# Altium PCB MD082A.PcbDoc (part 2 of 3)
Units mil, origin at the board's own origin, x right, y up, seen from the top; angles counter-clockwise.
Board outline 3650 x 4750 mil, 4 copper layers (Top Layer, GND Layer, Power Layer, Bottom Layer), stack 61.2 mil thick; 201 components, 105 nets, 514 pads, 1209 vias.
Unrouted connection lines stored in the file: 46.
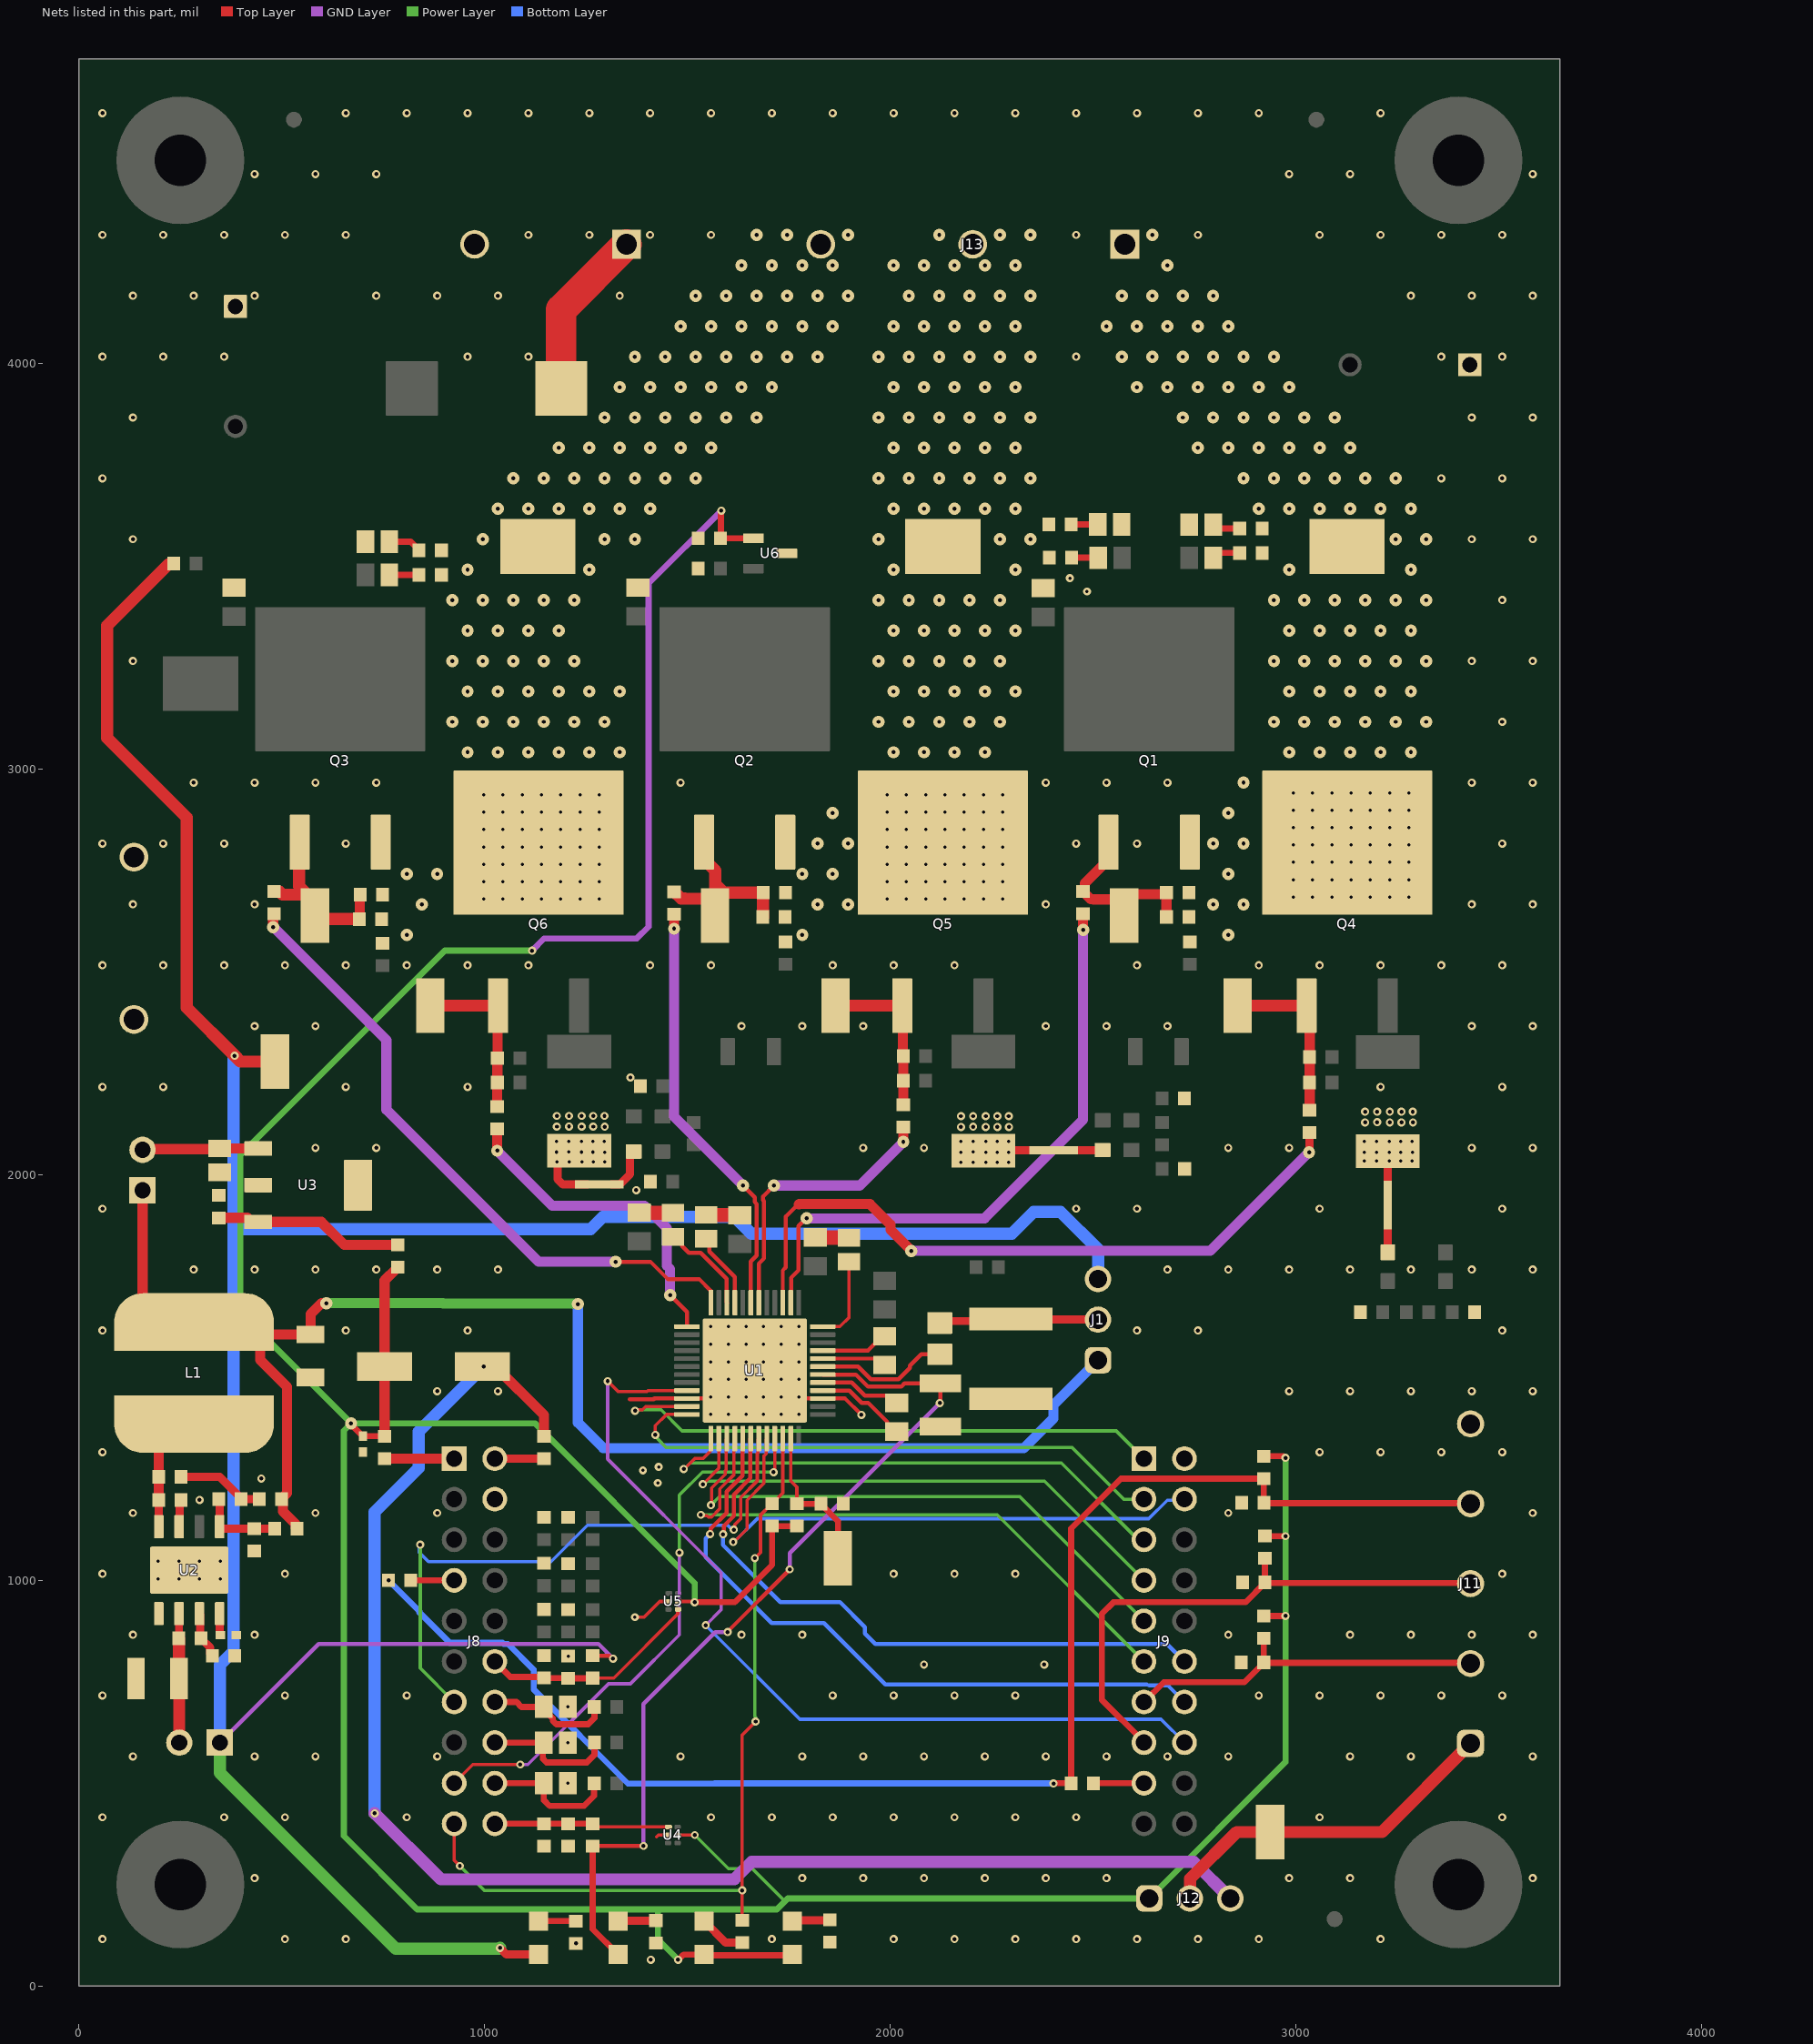
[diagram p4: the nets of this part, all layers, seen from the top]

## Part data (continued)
C23: library part CMP-0007275-4, "CAP, CERM, 56 pF, 100 V, +/- 5%, C0G/NP0, 0603", Cap_Case=0603, Manufacturer=MuRata, Supplier Part Number 1=490-1345-1-ND, TempCo=C0G/NP0, Tolerance_%=5%, Value1=Unknown, Value2=100V, ValueDisplayed=56pF
C30: library part CMP-0008656-2, "CAP, CERM, 47 uF, 25 V, +/- 20%, X5R, 1206_190", Cap_Case=1206, Manufacturer=TDK, Supplier Part Number 1=445-8047-1-ND, TempCo=X5R, Tolerance_%=20%, Value1=Unknown, Value2=25V, ValueDisplayed=47uF
C31 C32 C51 C52: library part CMP-0006857-5, "CAP, CERM, 0.1 uF, 16 V, +/- 5%, X7R, 0603", Cap_Case=0603, Manufacturer=Kemet, Supplier Part Number 1=399-1097-1-ND, TempCo=X7R, Tolerance_%=5%, Value1=Unknown, Value2=16V, ValueDisplayed=0.1uF
C33 C37 C38 C39 C40 C41 C42 C43 C45 C46 C47 C48: library part CMP-0006826-4, "CAP, CERM, 1000 pF, 16 V, +/- 10%, X7R, 0603", Cap_Case=0603, Manufacturer="Wurth Elektronik", Supplier Part Number 1=710-885012206034, TempCo=X7R, Tolerance_%=10%, Value1=Unknown, Value2=16V, ValueDisplayed=1000pF
C34 C35: library part CMP-0120361-1, "470 µF 100 V Aluminum Electrolytic Capacitors Radial, Can 2000 Hrs @ 105°C", Digikey Part Number=399-15666-ND, Leakage Current=470uA, Manufacturer=KEMET, Mouser Part Number=80-ESH477M100AM2AA, Operating Temperature Range="-40°C to +105°C", Tolerance_%=20%, ValueDisplayed=470uF
C36 C49 C50: library part CMP-0007796-3, "CAP, CERM, 470 pF, 50 V, +/- 10%, X7R, 0805", Cap_Case=0805, Manufacturer=Kemet, Supplier Part Number 1=399-1142-1-ND, TempCo=X7R, Tolerance_%=10%, Value1="0.688 ohm", Value2=50V, ValueDisplayed=470pF
C53 C54 C55 C56 C57: library part CMP-0079602-1, "CAP, CERM, 0.1 µF, 50 V,+/- 10%, X7R, AEC-Q200 Grade 1, 0603", Cap_Case=0603, Manufacturer=Kemet, Supplier Part Number 1=399-6856-1-ND, TempCo=X7R, Tolerance_%=10%, Value2=50V, ValueDisplayed=0.1µF
F1: library part CMP-0077200-3, "Fuse, 30 A, 250 VAC, 100 VDC, SMD", Irating_A=30A, Manufacturer=Littelfuse, PartNumber=0463030.ER, Supplier Part Number 1=F6439CT-ND
FID1 FID2 FID3: library part CMP-0077181-1, "Fiducial mark.  There is nothing to buy or mount.", Manufacturer=N/A
GND: library part CMP-0075110-1, "1mm Uninsulated Shorting Plug, 10.16mm spacing, TH", Manufacturer=Harwin, Supplier Part Number 1=952-1873-ND
H1 H2 H3 H4: library part CMP-0003611-1, Manufacturer=Keystone, Supplier Part Number 1=36-1902E-ND
H5 H6 H7 H8: library part CMP-0003617-1, "Machine Screw, Round, #4-40 x 1/4, Nylon, Philips panhead", Manufacturer="B&F Fastener Supply", Supplier Part Number 1=H542-ND
J1 J12: library part CMP-0054796-4, "Header, 2.54 mm, 3x1, Gold, TH", Manufacturer="Wurth Elektronik", Supplier Part Number 1=732-5316-ND
J6 J7: library part CMP-0054566-1, "Header, 100mil, 2x1, Gold, TH", Color=Black, Current_A=3A, Manufacturer="Sullins Connector Solutions", Supplier Part Number 1=S1011E-02-ND, Voltage_V=1.8kV
J8 J9: library part CMP-0075613-1, "Receptacle, 2.54mm, 10x2, Gold, TH", Color=Black, Current_A=6.3A, Manufacturer=Samtec, Voltage_V=550V
J10: library part CMP-0055527-1, "Terminal Block, 9.52mm, 2x1, R/A, TH", Color=Green, Current_A=32A, Manufacturer="Phoenix Contact", PartNumber=1902547, Supplier Part Number 1=277-5951-ND, Voltage_V=1kV
J11: library part CMP-0055532-1, "Terminal Block, 5mm, 5x1, R/A, TH", Color=Green, Current_A=16A, Manufacturer="Phoenix Contact", PartNumber=1792892, Supplier Part Number 1=277-2521-ND, Voltage_V=400V
J13: library part CMP-0055528-1, "Terminal Block, 9.52mm, 3x1, R/A, TH", Color=Green, Current_A=32A, Manufacturer="Phoenix Contact", PartNumber=1904150, Supplier Part Number 1=277-6184-ND, Voltage_V=1kV
L1: library part CMP-0057541-2, "Inductor, Drum Core, Ferrite, 68 uH, 1.1 A, 0.22 ohm, SMD", Manufacturer=Bourns, Supplier Part Number 1=SDR1006-680KLCT-ND, Value1="0.22 ohm", Value2=1.1A, ValueDisplayed=68uH
Logo1: library part CMP-0074844-1
Logo2: library part CMP-0074838-1, "Texas Instrument Corporate Signature"
Logo3: library part CMP-0074847-1, "FCC_disclaimer"
Logo4: library part CMP-0074769-3, Manufacturer="Texas Instruments"
LOGO5 LOGO7: library part CMP-0074837-2, "IEC 61010-1 Hot Surface Warning", Manufacturer="Texas Instruments"
LOGO6 LOGO8: library part CMP-0074835-1, "IEC 61010-1 High Voltage Warning"
MOTA MOTB MOTC VMOTOR: library part CMP-0055153-2, "Test Point, Compact, SMT", Manufacturer="Keystone Electronics", Supplier Part Number 1=36-5016TR-ND
nFAULT: library part CMP-0002829-3, "LED, Red, SMD", Color=red, Manufacturer=Lite-On, PartNumber=LTST-C170KRKT, Value1=W, Value2=2V
NT1 NT2 NT3: library part CMP-0078142-6, "Single point connection between nets.", Manufacturer=N/A
Q1 Q2 Q3 Q4 Q5 Q6: library part CMP-0001032-4, "MOSFET, N-CH, 100 V, 180 A, DDPAK", Alternate Manufacturer=None, Manufacturer=STMicroelectronics, Supplier Part Number 1=497-13585-1-ND, Value2="180 nC"
R1: library part CMP-0096837-1, "750 mOhms ±1% 0.333W, 1/3W Chip Resistor 0805 (2012 Metric) Current Sense Thin Film", Digikey Part Number=RL12S.75FCT-ND, Manufacturer=Susumu, Mouser Part Number=754-RL1220S-R75-F, Operating Temperature Range="-55°C to +125°C", Power_W=333mW, TempCo=0/+200ppm/°C, Tolerance_%=1%
R2 R3 R5 R25 R26 R27 R40 R41 R42: library part CMP-0020521-3, "RES, 2.7, 5%, 0.125 W, AEC-Q200 Grade 0, 0805", Manufacturer=Vishay-Dale, Power_W=125mW, Supplier Part Number 1=541-2.7ACT-ND, TempCo="200 ppm/C", Tolerance_%=5%, Value2=0.125W, Value_Code=2R70, ValueDisplayed=2.7
R4 R46 R47 R48: library part CMP-0025701-4, "RES, 10 k, 5%, 0.1 W, AEC-Q200 Grade 0, 0603", Manufacturer=Vishay-Dale, Power_W=100mW, Supplier Part Number 1=541-10KGCT-ND, TempCo="200 ppm/C", Tolerance_%=5%, Value2=0.1W, Value_Code=10k0, ValueDisplayed=10k
R6 R7 R8 R9 R10 R18 R28 R29 R30 R34 R35 R36 R37 R38 R39 R56: library part CMP-0081973-1, "RES, 0, 0%, 0.25 W, AEC-Q200 Grade 0, 0603", Manufacturer=Vishay-Dale, Power_W=250mW, Supplier Part Number 1=541-2779-1-ND, Tolerance_%=0%, Value2=0.25W, Value_Code=0
R11 R32 R45 R50 R53 R54: library part CMP-0097543-1, "10 Ohms ±0.1% 0.063W, 1/16W Chip Resistor 0603 (1608 Metric) Anti-Sulfur, Automotive AEC-Q200, Moisture Resistant Thin Film", Digikey Part Number=1712-CPF-A-0603B10RECT-ND, Manufacturer="TE Connectivity", Mouser Part Number=279-CPF-A-0603B10RE, Operating Temperature Range="-55°C to +155°C", Power_W=62.5mW, TempCo=25ppm/°C, Tolerance_%=0.1%
R14 R15: library part CMP-0025785-4, "RES, 330, 5%, 0.1 W, AEC-Q200 Grade 0, 0603", Manufacturer=Vishay-Dale, Power_W=100mW, Supplier Part Number 1=541-330GCT-ND, TempCo="200 ppm/C", Tolerance_%=5%, Value2=0.1W, Value_Code=330R, ValueDisplayed=330
R16 R17: library part CMP-0022458-4, "RES, 4.99 k, 1%, 0.1 W, AEC-Q200 Grade 0, 0603", Manufacturer=Vishay-Dale, Power_W=100mW, Supplier Part Number 1=541-4.99KHCT-ND, TempCo="100 ppm/C", Tolerance_%=1%, Value2=0.1W, Value_Code=4k99, ValueDisplayed=4.99k
R19: library part CMP-0025736-4, "RES, 1.0 M, 5%, 0.1 W, AEC-Q200 Grade 0, 0603", Manufacturer=Vishay-Dale, Power_W=100mW, Supplier Part Number 1=541-1.0MGCT-ND, TempCo="200 ppm/C", Tolerance_%=5%, Value2=0.1W, Value_Code=1M00, ValueDisplayed=1.0M
R20: library part CMP-0023236-4, "RES, 681 k, 1%, 0.1 W, 0603", Manufacturer=Yageo, Power_W=100mW, Supplier Part Number 1=311-681KHRCT-ND, TempCo="100 ppm/C", Tolerance_%=1%, Value2=0.1W, Value_Code=681k
R21: library part CMP-0023120-4, "RES, 453 k, 1%, 0.1 W, 0603", Manufacturer=Yageo, Power_W=100mW, Supplier Part Number 1=311-453KHRCT-ND, TempCo="100 ppm/C", Tolerance_%=1%, Value2=0.1W, Value_Code=453k
R22 R60 R75 R76 R77 R78: library part CMP-0021990-4, "RES, 100 k, 1%, 0.1 W, AEC-Q200 Grade 0, 0603", Manufacturer=Vishay-Dale, Power_W=100mW, Supplier Part Number 1=541-100KHCT-ND, TempCo="100 ppm/C", Tolerance_%=1%, Value2=0.1W, Value_Code=100k
R23: library part CMP-0025950-3, "RES, 100 k, 1%, 0.063 W, AEC-Q200 Grade 0, 0402", Manufacturer=Vishay-Dale, Power_W=63mW, Supplier Part Number 1=541-100KLCT-ND, TempCo="100 ppm/C", Tolerance_%=1%, Value2=0.063W, Value_Code=100k
R24: library part CMP-0023142-5, "RES, 49.9 k, 1%, 0.1 W, 0603", Manufacturer=Yageo, Power_W=100mW, Supplier Part Number 1=311-49.9KHRCT-ND, TempCo="100 ppm/C", Tolerance_%=1%, Value2=0.1W, Value_Code=49k9, ValueDisplayed=49.9k
R31 R33 R51: library part CMP-0015751-2, "RES, 0.005, 1%, 3 W, AEC-Q200 Grade 0, 2512", Manufacturer=Bourns, Power_W=3W, Supplier Part Number 1=CRE2512-FZ-R005E-3CT-ND, TempCo="75 ppm/C", Tolerance_%=1%, Value_Code=5L000, ValueDisplayed=0.005
R43 R44: library part CMP-0094724-1, "Jumper 0.25W, 1/4W Chip Resistor 1206 (3216 Metric) - Thick Film", Digikey Part Number=541-4170-1-ND, Manufacturer=Vishay, Mouser Part Number=71-CRCW12060000Z0EAC, Operating Temperature Range="-55°C to +155°C", Power_W=250mW
R49 R59 R63: library part CMP-0024720-2, "RES, 160, 0.5%, 0.1 W, 0603", Manufacturer="Yageo America", Power_W=100mW, TempCo="50 ppm/C", Tolerance_%=0.5%, Value2=0.1W, Value_Code=160R, ValueDisplayed=160
R52 R55 R65 R74 R86: library part CMP-0022663-4, "RES, 97.6 k, 1%, 0.1 W, AEC-Q200 Grade 0, 0603", Manufacturer=Vishay-Dale, Power_W=100mW, Supplier Part Number 1=541-97.6KHCT-ND, TempCo="100 ppm/C", Tolerance_%=1%, Value2=0.1W, Value_Code=97k6, ValueDisplayed=97.6k
R57: library part CMP-0025784-4, "RES, 330 k, 5%, 0.1 W, AEC-Q200 Grade 0, 0603", Manufacturer=Vishay-Dale, Power_W=100mW, Supplier Part Number 1=541-330KGCT-ND, TempCo="200 ppm/C", Tolerance_%=5%, Value2=0.1W, Value_Code=330k
R58: library part CMP-0025697-4, "RES, 0, 5%, 0.1 W, AEC-Q200 Grade 0, 0603", Manufacturer=Vishay-Dale, Power_W=100mW, Supplier Part Number 1=541-0.0GCT-ND, TempCo="200 ppm/C", Tolerance_%=5%, Value2=0.1W, Value_Code=0000, ValueDisplayed=0
R66 R80 R81 R82 R91: library part CMP-0022371-4, "RES, 3.01 k, 1%, 0.1 W, AEC-Q200 Grade 0, 0603", Manufacturer=Vishay-Dale, Power_W=100mW, Supplier Part Number 1=541-3.01KHCT-ND, TempCo="100 ppm/C", Tolerance_%=1%, Value2=0.1W, Value_Code=3k01, ValueDisplayed=3.01k
SH-J1 SH-J2 SH-J3 SH-J4: library part CMP-0003623-3, "Shunt, 100mil, Gold plated, Black", Alternate Manufacturer=3M, Alternate PartNumber=969102-0000-DA, Manufacturer=Samtec, Supplier Part Number 1=SAM8858-ND
U1: library part CMP-0120171-1, "12-V / 24-V Gate Driver Unit (GDU) with enhanced diagnostics", Manufacturer="Texas Instruments", Max Supply Voltage=60V, Min Supply Voltage=4V, Nominal Supply Current=20-25mA, Operating Temperature Range="-40°C to +175°C"
U1: library part CMP-0097571-1, "12-V / 24-V Automotive Gate Driver Unit (GDU) with enhanced diagnostics", Manufacturer="Texas Instruments", Max Supply Voltage=60V, Min Supply Voltage=4V, Operating Temperature Range="-40°C to +175°C"
U2: library part CMP-0080798-1, "100-V Low IQ Synchronous Buck Regulator, DDA0008E (SOIC-8)", Alternate Manufacturer="Texas Instruments"
U3: library part CMP-0080825-1, "500-mA, 25-V, Linear Voltage Regulators, DCY0004A (SOT-223-4)", Alternate Manufacturer="Texas Instruments", Alternate PartNumber=UA78M33CDCY
U4 U5: library part CMP-0043120-3, "4-Channel ESD Solution for High-Speed Differential Interface, DRY0006A (USON-6)", Breakdown Voltage(Min)(V)=9, Differential Capacitance(pF)=0.05, IO Capacitance(Typ)(pF)=0.8, IO Leakage Current(nA)=Jan-00, Manufacturer="Texas Instruments", Operating Temperature Range="-40 to 85 C", Rating=Catalog
U6: library part CMP-0088337-2, "Temperature Sensor Analog, Local -40°C ~ 150°C 10mV/°C SOT-23-3", Digikey Part Number=296-TMP235A2DBZRCT-ND, Manufacturer="Texas Instruments", Max Supply Voltage=5.5V, Min Supply Voltage=2.3V, Mouser Part Number=595-TMP235A2DBZR, Operating Supply Current=9uA, Operating Temperature Range="-40°C to +150°C"
ZZ1: library part CMP-0003616-3
ZZ2: library part CMP-0077236-1
ZZ3: library part CMP-0077237-1
ZZ4: library part CMP-0077238-1

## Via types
v1: diameter 20, hole 10, Top Layer to Bottom Layer, tented both sides, 424 vias
v2: diameter 30, hole 10, Top Layer to Bottom Layer, tented both sides, 355 vias
v3: diameter 30, hole 7.87, Top Layer to Bottom Layer, tented both sides, 294 vias
v4: diameter 19.68, hole 7.87, Top Layer to Bottom Layer, tented both sides, 76 vias
v5: diameter 20, hole 7.87, Top Layer to Bottom Layer, tented both sides, 54 vias
v6: diameter 19.68, hole 7.87, Top Layer to Bottom Layer, 4 vias
v7: diameter 20, hole 8, Top Layer to Bottom Layer, tented both sides, 1 vias
v8: diameter 30, hole 10, Top Layer to Bottom Layer, 1 vias

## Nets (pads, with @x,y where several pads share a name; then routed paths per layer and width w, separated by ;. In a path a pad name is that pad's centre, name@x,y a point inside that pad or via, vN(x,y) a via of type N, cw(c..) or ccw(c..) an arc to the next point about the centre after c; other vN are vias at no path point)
3.3V: 3.3V.1 3.3V_EXT.1 C9.2 C51.1 J12.1 nFAULT.1 R4.1 R6.1 R9.1 R46.1 R47.1 R48.1 R58.2 U4.5 U5.5 U6.1 | length 10519
  Top Layer w8: U4.5@1475.81,372.38 v1(1518.01,372.38) ; U5.5@1476.81,948 1516.01,948 v1(1517.88,946.13)
  Top Layer w15: v2(671,1387) 671,1384.2 C9.2@700.08,1355.12 R6.1@753.44,1355.12 ; v1(1476.81,65) 1478.16,65 1490.83,77.66 nFAULT.1@1541,77.66 1542.9,75.76 1756.52,75.76 3.3V.1@1758.43,77.66 ; v1(1517.88,946.13) 1616.82,946.13 1708.63,1037.94 R4.1@1708.63,1133.6 R9.1@1769.65,1133.6 ; v1(1583.25,3636.53) 1582.36,3635.65 1582.36,3569.29 C51.1@1581.47,3568.4 U6.1@1662.66,3568.4 ; R46.1@2920.34,912.23 v1(2973.94,912.23) ; R48.1@2920.34,1305.93 2968.78,1305.93 2972.58,1302.13 v1(2973.94,1302.13) ; R47.1@2923.14,1109.08 2923.26,1108.96 2973.82,1108.96 v1(2973.94,1108.84)
  Top Layer w25: R6.1@753.44,1355.12 3.3V_EXT.1@753.44,1526.84 753.44,1738.93 781.72,1767.21 781.72,1768.19 784.97,1771.44 R58.2@785.95,1771.44
  GND Layer w15: v1(1117,2552) 1147,2582 1375,2582 1404,2611 1404,3457.29 v1(1583.25,3636.53)
  Power Layer w8: v1(1518.01,372.38) 1600.76,289.63 1659.85,289.63 1740.31,209.17
  Power Layer w15: v2@672.4,1387 1123.96,1387 1517.88,993.08 v1(1517.88,946.13) ; v1(1117,2552) 902,2552 398.42,2048.42 398.42,1659.58 v2(671,1387) 653,1369 653,370 834,189 1427.21,189 ; v1(1476.81,65) 1427.21,114.6 1427.21,189 ; v1(2973.94,1302.13) v1(2973.94,1108.84) v1(2973.94,912.23) 2973.94,551.94 J12.1@2638,216 1747.13,216 1740.31,209.17 1720.13,189 1427.21,189
5V: 5V_EXT.1 J12.3 R7.2 | length 3693.8
  Top Layer w25: v2(997.93,1526.84) 1026.99,1526.84 1146,1407.84 R7.2@1146,1355.12
  GND Layer w30: v1(729,426) 891.87,263.13 1615.64,263.13 1658.51,306 2748,306 J12.3@2838,216
  Bottom Layer w30: v1(729,426) 729,1168 837.84,1276.84 837.84,1366.74 v2(997.93,1526.84)
BSTA: R2.2 U1.36 | length 211.8
  Top Layer w8: U1.36@1833.32,1625.27 1833.42,1625.37 1875.74,1625.37 1898.43,1648.05 R2.2@1898.43,1785.28
BSTB: R3.2 U1.45 | length 186.7
  Top Layer w10: R3.2@1546.04,1841.68 1553.97,1833.75 1553.97,1810.89 1616.79,1748.07 U1.45@1616.79,1684.32
BSTC: R5.2 U1.46 | length 237.7
  Top Layer w10: R5.2@1464.14,1846.68 1470.04,1846.68 1486.7,1830.03 1486.7,1824.12 1503.66,1807.15 1532.42,1807.15 1596.2,1743.38 1596.2,1685.23 U1.46@1597.1,1684.32
CPH: C1.1 U1.29 | length 203.5
  Top Layer w7.87: U1.29@1833.32,1487.47 U1.29@1855.23,1487.47
  Top Layer w10: U1.29@1855.23,1487.47 1904.53,1487.47 1937.02,1454.98 1998.46,1454.98 C1.1@2016.1,1437.35
CPL: C1.2 U1.28 | length 228.2
  Top Layer w10: U1.28@1833.32,1467.79 1898.94,1467.79 1929.61,1437.11 1945.47,1437.11 1992.56,1390.02 1992.56,1384.12 2010.19,1366.48 C1.2@2016.1,1366.48
CPTH: C3.1 U1.33 | length 165.8
  Top Layer w10: U1.33@1833.32,1566.21 1944.66,1566.21 1976.3,1597.85 C3.1@1986,1597.85
CPTL: C3.2 U1.32 | length 159.2
  Top Layer w7.87: U1.32@1833.32,1546.53 U1.32@1835.29,1546.53
  Top Layer w10: U1.32@1835.29,1546.53 1970.25,1546.53 C3.2@1986,1530.78
DRVOFF: J9.16 U1.9 | length 2239.8
  Top Layer w8: v1(1303.28,1490.73) 1328.28,1465.73 1400.33,1465.73 1402.38,1467.79 U1.9@1498.68,1467.79
  GND Layer w8: v1(1303.28,1490.73) 1303.28,1298.92 1583.36,1018.84 1583.36,927.83 v1(1544.95,889.42)
  Bottom Layer w8: v1(1544.95,889.42) 1776.76,657.61 2667.39,657.61 J9.16@2725,600
GHA: R28.1 U1.38 | length 1514.1
  Top Layer w10: U1.38@1754.58,1684.32 1755.49,1685.23 1755.49,1745.9 1773.73,1764.14 1773.73,1873.21 1792.52,1892 v2(1794,1892)
  Top Layer w25: v2(2475,2603) R28.1@2475,2642.44
  GND Layer w25: v2(1794,1892) 2232,1892 2475.15,2135.15 2475.15,2602.85 v2(2475,2603)
GHB: R29.1 U1.43 | length 1047.5
  Top Layer w10: v2(1636.86,1973.06) 1666,1943.92 1666,1932.34 1670.73,1927.61 1670.73,1800.81 1656.16,1786.23 U1.43@1656.16,1684.32
  Top Layer w25: v2(1467,2606) R29.1@1467,2641.44
  GND Layer w25: v2(1467,2606) 1467,2142.92 v2(1636.86,1973.06)
GHC: R30.1 U1.48 | length 1613.5
  Top Layer w10: v2(1322.51,1785.28) 1408.65,1785.28 1451.35,1742.58 1528.67,1742.58 1556.83,1714.42 1556.83,1685.23 U1.48@1557.73,1684.32
  Top Layer w25: v2(478.89,2610) 478.89,2641.07 R30.1@481,2643.18
  GND Layer w25: v2(478.89,2610) 757.96,2330.93 757.96,2160 1132.69,1785.28 v2(1322.51,1785.28)
GLA: R34.1 U1.39 | length 1722
  Top Layer w10: U1.39@1734.9,1684.32 1734.9,1763.86 1742.23,1771.19 1742.23,1896.42 1773.42,1927.61
  Top Layer w20: v2(3032,2055) 3033.44,2056.44 R34.1@3033.44,2103.44
  Top Layer w25: 1774.67,1926.36 1775.69,1927.37 1949.52,1927.37 2000.28,1876.61 2000.28,1863.72 v2(2052,1812)
  GND Layer w25: v2(2052,1812) 2789,1812 v2(3032,2055)
GLB: R35.1 U1.42 | length 706.4
  Top Layer w10: U1.42@1675.84,1684.32 1675.84,1780.64 1688.61,1793.4 1688.61,1935.02 1686.04,1937.58 1686.04,1945.86 v2(1713.24,1973.06)
  Top Layer w25: v2(2032,2080.67) R35.1@2032,2117.37
  GND Layer w25: v2(1713.24,1973.06) 1924.39,1973.06 v2(2032,2080.67)
GLC: R36.1 U1.1 | length 813.8
  Top Layer w10: v2(1457.25,1703) 1498.68,1661.57 U1.1@1498.68,1625.27
  Top Layer w25: v2(1031,2058.95) R36.1@1031,2112.37
  GND Layer w25: v2(1031,2058.95) 1166.95,1923 1394,1923 1449,1868 1449,1775.98 1457.25,1767.74 v2(1457.25,1703)
GND: C2.2 C5.2 C9.1 C16.2 C18.1 C20.1 C21.2 C30.2 C31.2 C32.2 C34.1 C35.1 C36.2 C37.2 C38.2 C39.2 C40.2 C41.2 C44.1 C45.2 C46.2 C47.2 C48.2 C49.2 C50.2 C51.2 C52.2 C53.1 C54.1 C55.1 C56.1 C57.1 GND.1 GND.2 J8.4 J9.2 J10.2 J11.5 NT1.2 NT2.2 NT3.2 R15.1 R16.1 R17.1 R23.1 R24.1 R31.1 R33.1 R40.1 R41.1 R42.1 R51.1 R57.1 R66.1 R80.1 R81.1 R82.1 R91.1 U1.10 U1.27 U1.49 U2.1 U2.9@272,1025 U3.2 U3.4 U4.2 U5.2 U6.3 | length 934.7
  Top Layer w8: v7(1370.3,909.3) 1393.03,909.3 1431.73,948 U5.2@1453.19,948 ; 1424.01,367.97 1428.42,372.38 U4.2@1452.19,372.38
  Top Layer w10: 1357.45,1446.68 1417.1,1446.68 1418.53,1448.1 U1.10@1498.68,1448.1 1553.8,1448.1 v4(1557.73,1452.04) ; v4(1774.27,1452.04) 1778.2,1448.1 U1.27@1833.32,1448.1 1888.42,1448.1 v1(1928.68,1407.84)
  Top Layer w20: R51.1@1233,2058.95 1210.89,2058.95 1179.55,2027.61 1179.55,1988.93 1192.84,1975.64 NT3.2@1252.75,1975.64 ; R33.1@2230.87,2070.27 R33.1@2232.3,2071.71 ; R33.1@2230.94,2060.39 NT2.2@2372.31,2060.39 ; NT1.2@3226,1954.64 R31.1@3226,2057.95
  other v1: 1409.72,65 1225.23,105.22 58,116 508,116 658,116 1708,116 2008,116 2158,116 2308,116 2458,116 2608,116 2758,116 2908,116 3208,116 433,266 1783,266 1933,266 2083,266 2233,266 2383,266 2533,266 2983,266 3133,266 3583,266 58,416 358,416 508,416 808,416 1558,416 1708,416 1858,416 2008,416 2158,416 2308,416 2458,416 3058,416 3508,416 133,566 433,566 583,566 883,566 1483,566 1783,566 1933,566 2083,566 2233,566 2383,566 2533,566 2683,566 2833,566 3133,566 3283,566 3583,566 58,716 508,716 808,716 1858,716 2008,716 2158,716 2308,716 2908,716 3058,716 3208,716 3358,716 3508,716 2083,792.27 2379.22,792.27 133,866 433,866 1633,866 1783,866 2833,866 3133,866 3283,866 3433,866 3583,866 58,1016 508,1016 2008,1016 2158,1016 2308,1016 3508,1016 133,1166 583,1166 883,1166 2833,1166 3583,1166 297.59,1198.22 449.61,1250.89 58,1316 3058,1316 3208,1316 3358,1316 3508,1316 883,1466 1033,1466 2983,1466 3133,1466 3283,1466 3433,1466 3583,1466 58,1616 658,1616 958,1616 2608,1616 2758,1616 3508,1616 283,1766 433,1766 583,1766 733,1766 883,1766 1033,1766 2683,1766 2833,1766 2983,1766 3133,1766 3283,1766 3433,1766 3583,1766 58,1916 2458,1916 2608,1916 3058,1916 3508,1916 1373.84,1961.52 583,2066 733,2066 1933,2066 2083,2066 2833,2066 2983,2066 3433,2066 3583,2066 2292.11,2117.37 1178,2118.26 1238.97,2118.26 1267.58,2118.26 1296,2118 2174.11,2117.63 2204.09,2118.03 2235.08,2117.63 2263.69,2117.63 1207.98,2118.66 3288,2128.47 3170,2128.73 3199.98,2129.13 3230.97,2128.73 3259.58,2128.73 2174.11,2144.07 2204.09,2144.07 2235.08,2144.07 2263.69,2144.07 2291.58,2144.07 1178,2144.69 1207.98,2144.69 1238.97,2144.69 1267.58,2144.69 1295.47,2144.69 3170,2155.16 3199.98,2155.16 3230.97,2155.16 3259.58,2155.16 3287.47,2155.16 58,2216 208,2216 658,2216 958,2216 3208,2216 3508,2216 1359.38,2239.37 433,2366 583,2366 1633,2366 1783,2366 1933,2366 2383,2366 2533,2366 2683,2366 3433,2366 3583,2366 58,2516 208,2516 358,2516 508,2516 658,2516 808,2516 958,2516 1108,2516 1408,2516 1558,2516 1858,2516 2008,2516 2158,2516 2608,2516 2908,2516 3058,2516 3208,2516 3358,2516 3508,2516 133,2666 433,2666 2383,2666 3433,2666 3583,2666 58,2816 208,2816 358,2816 658,2816 2458,2816 2608,2816 3508,2816 283,2966 433,2966 583,2966 733,2966 1483,2966 2383,2966 2533,2966 2683,2966 3433,2966 3583,2966 3508,3116 133,3266 3433,3266 3583,3266 3508,3416 133,3566 3433,3566 3583,3566 58,3716 3358,3716 3508,3716 133,3866 3433,3866 3583,3866 58,4016 208,4016 358,4016 958,4016 1108,4016 2458,4016 3358,4016 3508,4016 133,4166 283,4166 433,4166 733,4166 883,4166 1033,4166 1333,4166 3283,4166 3433,4166 3583,4166 58,4316 208,4316 358,4316 508,4316 658,4316 1108,4316 1258,4316 1408,4316 1558,4316 2458,4316 2758,4316 3058,4316 3208,4316 3358,4316 3508,4316 433,4466 583,4466 733,4466 2983,4466 3133,4466 3583,4466 58,4616 658,4616 808,4616 958,4616 1108,4616 1258,4616 1408,4616 1558,4616 1708,4616 1858,4616 2008,4616 2158,4616 2308,4616 2458,4616 2608,4616 2758,4616 2908,4616 3208,4616
  other v4: 195.23,1003.35 348.77,1003.35 195.23,1046.65 348.77,1046.65 1557.73,1408.73 1557.73,1408.73 1601.04,1408.73 1601.04,1408.73 1644.35,1408.73 1644.35,1408.73 1687.65,1408.73 1687.65,1408.73 1730.96,1408.73 1730.96,1408.73 1774.27,1408.73 1774.27,1408.73 1557.73,1452.04 1601.04,1452.04 1601.04,1452.04 1644.35,1452.04 1644.35,1452.04 1687.65,1452.04 1687.65,1452.04 1730.96,1452.04 1730.96,1452.04 1774.27,1452.04 1557.73,1495.35 1557.73,1495.35 1601.04,1495.35 1601.04,1495.35 1644.35,1495.35 1644.35,1495.35 1687.65,1495.35 1687.65,1495.35 1730.96,1495.35 1730.96,1495.35 1774.27,1495.35 1774.27,1495.35 1557.73,1538.65 1557.73,1538.65 1601.04,1538.65 1601.04,1538.65 1644.35,1538.65 1644.35,1538.65 1687.65,1538.65 1687.65,1538.65 1730.96,1538.65 1730.96,1538.65 1774.27,1538.65 1774.27,1538.65 1557.73,1581.96 1557.73,1581.96 1601.04,1581.96 1601.04,1581.96 1644.35,1581.96 1644.35,1581.96 1687.65,1581.96 1687.65,1581.96 1730.96,1581.96 1730.96,1581.96 1774.27,1581.96 1774.27,1581.96 1557.73,1625.27 1557.73,1625.27 1601.04,1625.27 1601.04,1625.27 1644.35,1625.27 1644.35,1625.27 1687.65,1625.27 1687.65,1625.27 1730.96,1625.27 1730.96,1625.27 1774.27,1625.27 1774.27,1625.27
  other v5: 1205.06,500 1205.06,600 1205.06,688.06 1206.25,813.27 1427,1239.89 1390.24,1271.11 1428.89,1279.61 2174,2030.32 2203.98,2030.32 2234.97,2030.32 2263.58,2030.32 2291.47,2030.32 1178.53,2031.59 1208.51,2031.59 1239.5,2031.59 1268.1,2031.59 1296,2031.59 3168.53,2033.37 3198.51,2033.37 3229.5,2033.37 3258.1,2033.37 3286,2033.37 1295.47,2055.26 2174,2055.26 2234.97,2055.26 2263.58,2055.26 2292,2055 3168.53,2055.04 3198.51,2055.43 3229.5,2055.04 3258.1,2055.04 3286.53,2054.78 1177.47,2055.52 1207.45,2055.92 1238.45,2055.52 1267.05,2055.52 2203.98,2055.66 3168.53,2081.47 3198.51,2081.47 3229.5,2081.47 3258.1,2081.47 3286,2081.47 1177.47,2081.95 1207.45,2081.95 1238.45,2081.95 1267.05,2081.95 1294.95,2081.95 2174,2081.69 2203.98,2081.69 2234.97,2081.69 2263.58,2081.69 2291.47,2081.69 2484.75,3437.19 2442.53,3469.84
  other v6: 246.41,1003.35 297.59,1003.35 246.41,1046.65 297.59,1046.65
GVDD: C5.1 GVDD.1 R86.2 U1.30 | length 2184.2
  Top Layer w10: R86.2@1266.49,344.88 1266.91,345.3 v1(1391.4,345.3) ; v1(1599.13,872.44) 1599.13,874.13 v1(1752,1027) ; U1.30@1833.32,1507.16 1914.96,1507.16 1944.72,1477.39 2027.28,1477.39 2035.04,1485.15 C5.1@2123,1485.15 2123,1438.11 v1(2122,1437.11)
  Top Layer w15: R86.2@1266.49,344.88 1266.49,140.17 GVDD.1@1329,77.66
  GND Layer w10: v1(1391.4,345.3) 1391.4,695.24 1568.6,872.44 v1(1599.13,872.44) ; v1(1752,1027) 1752,1067.11 v1(2122,1437.11)
HALL_A: C39.1 J9.13 J11.2 R46.2 | length 907.5
  Top Layer w15: J9.13@2625,700 2673.71,748.71 2872.19,748.71 2920.34,796.87 C39.1@2920.34,797.85 ; R46.2@2921.33,857.11 R46.2@2920.34,857.11 C39.1@2920.34,797.85 ; J11.2@3430,795 3428.57,796.43 2921.77,796.43 C39.1@2920.34,797.85
HALL_B: C38.1 J9.15 J11.3 R47.2 | length 1362.3
  Top Layer w15: J9.15@2625,600 2625,602 2521,706 2521,917 2550,946 2875.43,946 2923.14,993.72 C38.1@2923.14,994.7 ; R47.2@2923.14,1053.96 C38.1@2923.14,994.7 ; J11.3@3430,991.85 3428.57,993.28 2924.57,993.28 C38.1@2923.14,994.7
HALL_C: C37.1 J11.4 R8.1 R10.1 R48.2 | length 3644.1
  Top Layer w15: v1(2402.05,499.42) 2402.64,500 R10.1@2445.44,500 2445.44,1127.94 2568.32,1250.81 R48.2@2920.34,1250.81 2920.5,1250.66 2920.5,1191.71 C37.1@2920.66,1191.55 2922.08,1190.13 3428.57,1190.13 J11.4@3430,1188.7
  Bottom Layer w15: v1(763.1,1000) 839.14,923.96 839.14,920.97 914.22,845.89 1044.01,845.89 1046.89,843 1057.54,843 1120.89,779.65 1120.89,731.2 1353.09,499 1566.23,499 1566.64,499.42 v1(2402.05,499.42)
HALL_PWR: HALL_EXT.1 J11.1 J12.2 | length 878.3
  Top Layer w30: J12.2@2738,216 2738.86,216.86 2738.86,264.71 2853.72,379.57 HALL_EXT.1@2935.94,379.57 3211.42,379.57 J11.1@3430,598.15
INHA: J9.1 U1.11 | length 1436.7
  Top Layer w8: v1(1371,1418) 1373.3,1420.3 1389.09,1420.3 1397,1428.21 1498.47,1428.21 U1.11@1498.68,1428.42
  Power Layer w8: v1(1371,1418) 1373.2,1420.2 1434.8,1420.2 1486.61,1368.39 2556.61,1368.39 J9.1@2625,1300
INHB: J9.5 U1.13 | length 1331.7
  Top Layer w7.87: v1(1490.58,1274.58) 1492.59,1274.58 1518.01,1300 1538,1300 1555.76,1317.76 U1.13@1555.76,1347.71
  Power Layer w7.87: v1(1490.58,1274.58) 1492.59,1274.58 1507.01,1289 2421.58,1289 2595.74,1114.84 ; 2595.78,1114.84 2610.62,1100 J9.5@2625,1100
INHC: J9.9 U1.15 | length 1382.9
  Top Layer w7.87: v1(1557.79,1185.53) 1559.53,1187.27 1559.53,1227.68 1593.16,1261.32 1593.16,1269.89 1595.13,1271.86 1595.13,1317.51 1595.13,1347.71 U1.15@1597.1,1349.68
  Power Layer w7.87: v1(1557.79,1185.53) 1578.28,1206.02 2318.98,1206.02 J9.9@2625,900
INLA: J9.3 U1.12 | length 1384.4
  Top Layer w7.87: v1(1420.83,1358.3) 1420.83,1381.3 1448.26,1408.73 U1.12@1498.68,1408.73
  Power Layer w7.87: v1(1420.83,1358.3) 1420.83,1355.02 1427,1348.84 1427,1348 1447.39,1327.61 2448,1327.61 2575.61,1200 J9.3@2625,1200
INLB: J9.7 U1.14 | length 1320.7
  Top Layer w7.87: v1(1538,1237) 1577.42,1276.42 U1.14@1577.42,1349.68
  Power Layer w7.87: v1(1538,1237) 1540.82,1237 1548.68,1244.86 2380.14,1244.86 J9.7@2625,1000
INLC: J9.11 U1.16 | length 1488.3
  Top Layer w7.87: v1(1532.67,1161.54) 1534.99,1159.22 1548.12,1159.22 1551.28,1156.05 1559.16,1156.05 1579.6,1176.49 1579.6,1225.48 1614.82,1260.7 1614.82,1317.51 1614.82,1347.71 U1.16@1616.79,1349.68
  Power Layer w7.87: v1(1532.67,1161.54) 2263.46,1161.54 J9.11@2625,800
ISENA: C36.1 J8.14 R59.1 | length 309.7
  Top Layer w15: J8.14@1025,700 1078.68,700 1090.62,688.06 C36.1@1146,688.06 1146,682.16 1168.03,660.13 1168.03,654.14 1177.03,645.13 1255.44,645.13 1270.85,660.54 1270.85,687.44 R59.1@1270.22,688.06
ISENB: C49.1 J8.16 R49.1 | length 330.9
  Top Layer w15: J8.16@1025,600 C49.1@1146,600 1143.81,597.81 1143.81,559.79 1152.6,551 1252.13,551 1271,569.87 R49.1@1271,600
ISENC: C50.1 J8.18 R63.1 | length 334.2
  Top Layer w15: J8.18@1025,500 C50.1@1146,500 1146,458.15 1160.15,444 1245,444 1269.63,468.63 1269.63,499.41 R63.1@1270.22,500
MOTA: C12.2 C15.2 C26.1 J13.1 MOTA.1 Q1.3 Q4.2 R22.2 R37.2
  other v2: 2833,2591 2795.5,2666 2870.5,2666 2833,2741 2795.5,2816 2870.5,2816 2833,2891 2870.5,2966 2983,3041 3058,3041 3133,3041 3208,3041 3283,3041 2945.5,3116 3020.5,3116 3095.5,3116 3170.5,3116 3245.5,3116 3320.5,3116 2983,3191 3058,3191 3133,3191 3208,3191 3283,3191 2945.5,3266 3020.5,3266 3095.5,3266 3170.5,3266 3245.5,3266 3320.5,3266 2983,3341 3058,3341 3133,3341 3208,3341 3283,3341 2945.5,3416 3020.5,3416 3095.5,3416 3170.5,3416 3245.5,3416 3320.5,3416 2983,3491 3283,3491 3245.5,3566 3320.5,3566 2908,3641 2983,3641 3058,3641 3133,3641 3208,3641 3283,3641 2870.5,3716 2945.5,3716 3020.5,3716 3095.5,3716 3170.5,3716 3245.5,3716 2758,3791 2833,3791 2908,3791 2983,3791 3058,3791 3133,3791 2720.5,3866 2795.5,3866 2870.5,3866 2945.5,3866 3020.5,3866 3095.5,3866 2608,3941 2683,3941 2758,3941 2833,3941 2908,3941 2983,3941 2570.5,4016 2645.5,4016 2720.5,4016 2795.5,4016 2870.5,4016 2945.5,4016 2533,4091 2608,4091 2683,4091 2758,4091 2833,4091 2570.5,4166 2645.5,4166 2720.5,4166 2795.5,4166 2683,4241 2645.5,4316
  other v3: 2993,2684 3040.5,2684 3088,2684 3135.5,2684 3183,2684 3230.5,2684 3278,2684 2993,2726.83 3040.5,2726.83 3088,2726.83 3135.5,2726.83 3183,2726.83 3230.5,2726.83 3278,2726.83 2993,2769.67 3040.5,2769.67 3088,2769.67 3135.5,2769.67 3183,2769.67 3230.5,2769.67 3278,2769.67 2993,2812.5 3040.5,2812.5 3088,2812.5 3135.5,2812.5 3183,2812.5 3230.5,2812.5 3278,2812.5 2993,2855.33 3040.5,2855.33 3088,2855.33 3135.5,2855.33 3183,2855.33 3230.5,2855.33 3278,2855.33 2993,2898.17 3040.5,2898.17 3088,2898.17 3135.5,2898.17 3183,2898.17 3230.5,2898.17 3278,2898.17 2993,2941 3040.5,2941 3088,2941 3135.5,2941 3183,2941 3230.5,2941 3278,2941
MOTB: C13.2 C17.2 C24.1 J13.2 MOTB.1 Q2.3 Q5.2 R38.2 R60.2
  other v2: 1783,2591 1820.5,2666 1895.5,2666 1783,2741 1858,2741 1820.5,2816 1895.5,2816 1858,2891 2008,3041 2083,3041 2158,3041 2233,3041 1970.5,3116 2045.5,3116 2120.5,3116 2195.5,3116 2270.5,3116 2008,3191 2083,3191 2158,3191 2233,3191 2308,3191 1970.5,3266 2045.5,3266 2120.5,3266 2195.5,3266 2270.5,3266 2008,3341 2083,3341 2158,3341 2233,3341 2308,3341 1970.5,3416 2045.5,3416 2120.5,3416 2195.5,3416 2270.5,3416 2008,3491 2308,3491 1970.5,3566 2270.5,3566 2345.5,3566 2008,3641 2083,3641 2158,3641 2233,3641 2308,3641 1970.5,3716 2045.5,3716 2120.5,3716 2195.5,3716 2270.5,3716 2345.5,3716 2008,3791 2083,3791 2158,3791 2233,3791 2308,3791 1970.5,3866 2045.5,3866 2120.5,3866 2195.5,3866 2270.5,3866 2345.5,3866 2008,3941 2083,3941 2158,3941 2233,3941 2308,3941 1970.5,4016 2045.5,4016 2120.5,4016 2195.5,4016 2270.5,4016 2345.5,4016 2008,4091 2083,4091 2158,4091 2233,4091 2308,4091 2045.5,4166 2120.5,4166 2195.5,4166 2270.5,4166 2345.5,4166 2008,4241 2083,4241 2158,4241 2233,4241 2308,4241 2120.5,4316 2270.5,4316 2345.5,4316
  other v3: 1992,2679 2039.5,2679 2087,2679 2134.5,2679 2182,2679 2229.5,2679 2277,2679 1992,2721.83 2039.5,2721.83 2087,2721.83 2134.5,2721.83 2182,2721.83 2229.5,2721.83 2277,2721.83 1992,2764.67 2039.5,2764.67 2087,2764.67 2134.5,2764.67 2182,2764.67 2229.5,2764.67 2277,2764.67 1992,2807.5 2039.5,2807.5 2087,2807.5 2134.5,2807.5 2182,2807.5 2229.5,2807.5 2277,2807.5 1992,2850.33 2039.5,2850.33 2087,2850.33 2134.5,2850.33 2182,2850.33 2229.5,2850.33 2277,2850.33 1992,2893.17 2039.5,2893.17 2087,2893.17 2134.5,2893.17 2182,2893.17 2229.5,2893.17 2277,2893.17 1992,2936 2039.5,2936 2087,2936 2134.5,2936 2182,2936 2229.5,2936 2277,2936
MOTC: C14.2 C19.2 C25.1 J13.3 MOTC.1 Q3.3 Q6.2 R56.2 R75.2
  other v2: 808,2591 845.5,2666 808,2741 883,2741 958,3041 1033,3041 1108,3041 1183,3041 1258,3041 1333,3041 920.5,3116 995.5,3116 1070.5,3116 1145.5,3116 1220.5,3116 1295.5,3116 958,3191 1033,3191 1108,3191 1183,3191 1258,3191 1333,3191 920.5,3266 995.5,3266 1070.5,3266 1145.5,3266 1220.5,3266 958,3341 1033,3341 1108,3341 1183,3341 920.5,3416 995.5,3416 1070.5,3416 1145.5,3416 1220.5,3416 958,3491 1258,3491 995.5,3566 1295.5,3566 1370.5,3566 1033,3641 1108,3641 1183,3641 1258,3641 1333,3641 1408,3641 1070.5,3716 1145.5,3716 1220.5,3716 1295.5,3716 1370.5,3716 1445.5,3716 1520.5,3716 1183,3791 1258,3791 1333,3791 1408,3791 1483,3791 1558,3791 1295.5,3866 1370.5,3866 1445.5,3866 1520.5,3866 1595.5,3866 1670.5,3866 1333,3941 1408,3941 1483,3941 1558,3941 1633,3941 1708,3941 1370.5,4016 1445.5,4016 1520.5,4016 1595.5,4016 1670.5,4016 1745.5,4016 1820.5,4016 1483,4091 1558,4091 1633,4091 1708,4091 1783,4091 1858,4091 1520.5,4166 1595.5,4166 1670.5,4166 1745.5,4166 1820.5,4166 1895.5,4166 1633,4241 1708,4241 1783,4241 1858,4241 1670.5,4316 1745.5,4316 1895.5,4316
  other v3: 997.75,2679 1045.25,2679 1092.75,2679 1140.25,2679 1187.75,2679 1235.25,2679 1282.75,2679 997.75,2721.83 1045.25,2721.83 1092.75,2721.83 1140.25,2721.83 1187.75,2721.83 1235.25,2721.83 1282.75,2721.83 997.75,2764.67 1045.25,2764.67 1092.75,2764.67 1140.25,2764.67 1187.75,2764.67 1235.25,2764.67 1282.75,2764.67 997.75,2807.5 1045.25,2807.5 1092.75,2807.5 1140.25,2807.5 1187.75,2807.5 1235.25,2807.5 1282.75,2807.5 997.75,2850.33 1045.25,2850.33 1092.75,2850.33 1140.25,2850.33 1187.75,2850.33 1235.25,2850.33 1282.75,2850.33 997.75,2893.17 1045.25,2893.17 1092.75,2893.17 1140.25,2893.17 1187.75,2893.17 1235.25,2893.17 1282.75,2893.17 997.75,2936 1045.25,2936 1092.75,2936 1140.25,2936 1187.75,2936 1235.25,2936 1282.75,2936
Net3.3V_2: 3.3V.2 R15.2 | length 93.9
  Top Layer w20: 3.3V.2@1758.43,160.34 1760.04,161.95 1849.39,161.95 R15.2@1851,163.56
NetC2_1: C2.1 J1.2 R1.1 | length 395.1
  Top Layer w20: R1.1@2122,1634.22 2126.89,1639.11 2292.11,1639.11 C2.1@2296.29,1643.29 ; C2.1@2297,1644 C2.1@2296.29,1643.29 ; J1.2@2512,1642.58 2511.29,1643.29 C2.1@2296.29,1643.29
NetC6_2: C6.2 R2.1 | length 83.7
  Top Layer w35: C6.2@1815.15,1845.24 1815.6,1844.79 1897.97,1844.79 R2.1@1898.43,1844.33
NetC7_2: C7.2 R3.1 | length 83.7
  Top Layer w35: R3.1@1546.04,1900.74 1546.58,1900.19 1628.77,1900.19 C7.2@1629.31,1899.64
NetC8_2: C8.2 R5.1 | length 83.7
  Top Layer w35: C8.2@1380.86,1906.64 1381.31,1906.19 1463.68,1906.19 R5.1@1464.14,1905.74
NetC11_1: C11.1 U2.7 | length 67.6
  Top Layer w20: U2.7@247,1132.28 248.81,1134.09 248.81,1195.25 C11.1@251.56,1198
NetC11_2: C11.2 L1.1 R20.1 U2.8 | length 308.7
  Top Layer w20: C11.2@196.44,1198 196.72,1197.72 196.72,1132.56 U2.8@197,1132.28
  Top Layer w25: C11.2@196.44,1198 196.66,1198.22 196.66,1254.78 R20.1@196.88,1255 196.88,1331.08 250.81,1385 L1.1@284,1385
NetC12_1: C12.1 R25.1 | length 70.2
  Top Layer w15: R25.1@2795.83,3520.1 2807.93,3532.2 C12.1@2861,3532.2
NetC13_1: C13.1 R26.1 | length 65.2
  Top Layer w15: C13.1@2446.81,3520.55 R26.1@2511.98,3520.55
NetC14_1: C14.1 R27.1 | length 73.1
  Top Layer w15: R27.1@765.35,3478 C14.1@838.44,3478
NetC15_1: C15.1 GHA.1 Q1.1 R22.1 R28.2 | length 494.4
  Top Layer w25: R28.2@2475,2697.56 R28.2@2475.98,2697.56 ; Q1.1@2538,2819.43 2538,2776.67 2479.23,2717.9 2479.23,2700.81 R28.2@2475.98,2697.56 ; GHA.1@2568.56,2663.36 2553.65,2678.27 2500.47,2678.27 2500.17,2678.56 2494,2678.56 2479.23,2693.33 2479.23,2694.31 R28.2@2475.98,2697.56 ; GHA.1@2576.15,2670.95 2576.15,2655.77 GHA.1@2576.15,2638.45 2576.15,2668.27 2598.65,2690.77 2677.19,2690.77 2680.44,2694.02 C15.1@2680.44,2695 R22.1@2680.44,2634.75
NetC16_1: C16.1 J7.2 U3.1 | length 290
  Top Layer w25: J7.2@157,2061 157,2064.55 158.79,2062.76 345.24,2062.76 C16.1@347,2064.53 U3.1@441.96,2064.54
NetC17_1: C17.1 GHB.1 Q2.1 R29.2 R60.1 | length 459.1
  Top Layer w30: R29.2@1467,2696.56 1467.98,2696.56 1484.48,2680.06 1493.21,2680.06 1493.32,2679.95 1559.15,2679.95 1568.15,2670.95 1568.15,2716.45 ; Q2.1@1541,2819.43 1541,2776.67 1568.15,2749.52 1568.15,2716.45 ; R60.1@1685.88,2634.75 1686.16,2635.03 1686.16,2694.72 C17.1@1686.44,2695 1589.59,2695 1568.15,2716.45
NetC19_1: C19.1 GHC.1 Q3.1 R30.2 R75.1 | length 456.2
  Top Layer w25: R75.1@691.44,2629.75 692.44,2630.75 692.44,2689 C19.1@693.44,2690
  Top Layer w30: R30.2@481,2698.29 481.75,2697.55 494.9,2697.55 502.44,2690 GHC.1@562.15,2690 ; Q3.1@544,2819.43 544,2809 543,2808 543,2710.09 582.15,2670.95 GHC.1@582.15,2638.45 590.84,2629.75 R75.1@691.44,2629.75
NetC21_1: C21.1 J6.2 R19.2 U2.2 | length 319.9
  Top Layer w20: R19.2@246.44,857 246.72,857.28 246.72,917.44 U2.2@247,917.72
  Top Layer w30: R19.2@246.44,857 246.72,856.72 246.72,758.28 C21.1@247,758 247.3,757.7 247.3,600.89 246.41,600 J6.2@247.59,600
NetC22_2: C22.2 C23.1 R20.2 | length 216.8
  Top Layer w20: R20.2@252,1255 347.2,1255 393.81,1208.39 393.81,1205.75 C23.1@399.56,1200 C22.2@444.44,1200
NetC23_2: C23.2 R21.1 R24.2 U2.5 | length 208.1
  Top Layer w20: C23.2@344.44,1200 347,1197.44 U2.5@347,1132.28 347,1129.37 348.81,1127.56 R24.2@432.03,1127.56 432.31,1127.28 482.16,1127.28 R21.1@482.44,1127
NetC24_2: C24.2 R41.2 | length 65.2
  Top Layer w15: C24.2@2446,3602.45 R41.2@2511.17,3602.45
NetC25_2: C25.2 R42.2 | length 82.6
  Top Layer w15: R42.2@765.35,3559.9 817.77,3559.9 838.44,3539.23 C25.2@838.44,3538.25
NetC26_2: C26.2 R40.2 | length 69.1
  Top Layer w15: R40.2@2795.83,3602 2805.39,3592.45 C26.2@2861,3592.45
NetC27_1: C27.1 GLA.1 Q4.1 R34.2 R76.1 | length 430.9
  Top Layer w25: Q4.1@3026,2416.43 3033.44,2408.98 R76.1@3033.44,2226.56 R34.2@3033.44,2158.56
  Top Layer w30: GLA.1@2856,2416.43 Q4.1@3026,2416.43
NetC28_1: C28.1 GLB.1 Q5.1 R35.2 R77.1 | length 409.3
  Top Layer w25: Q5.1@2029.5,2416.43 2030.75,2415.18 2030.75,2293.25 C28.1@2032,2292 R77.1@2032,2231.75 R35.2@2032,2172.49
  Top Layer w30: GLB.1@1865.21,2416.43 Q5.1@2029.5,2416.43
NetC29_1: C29.1 GLC.1 Q6.1 R36.2 R78.1 | length 416.8
  Top Layer w25: R36.2@1031,2167.49 1031.22,2167.71 1031.22,2226.53 R78.1@1031.44,2226.75 C29.1@1031.44,2287 1032.22,2287.78 1032.22,2415.65 Q6.1@1033,2416.43
  Top Layer w30: GLC.1@866,2416.43 Q6.1@1033,2416.43
NetC31_1: C31.1 R58.1 U3.3 | length 468.7
  Top Layer w25: C31.1@345,1893.44 415.24,1893.44 425.24,1883.45 U3.3@441.97,1883.45 597.55,1883.45 654.44,1826.56 R58.1@785.95,1826.56
NetC32_1: C32.1 R9.2 U1.23 VREF_EXT.1 | length 378
  Top Layer w8: U1.23@1754.58,1349.68 1754.58,1244.86 1769.65,1229.79 R9.2@1769.65,1188.72
  Top Layer w15: R9.2@1769.65,1188.72 C32.1@1828.91,1188.72 1828.91,1187.73 1870.79,1145.85 VREF_EXT.1@1870.79,1054.57
NetF1_2: F1.2 J10.1 | length 421.8
  Top Layer w75: F1.2@1188.81,3938 1188.81,4131.81 J10.1@1350,4293
NetGVDD_2: GVDD.2 R17.2 | length 93.5
  Top Layer w20: GVDD.2@1329,160.34 1329.61,160.95 1421.39,160.95 R17.2@1422,161.56
NetJ8_1: J8.1 R6.2 | length 171.6
  Top Layer w25: R6.2@753.44,1300 J8.1@925,1300
NetJ8_2: J8.2 R7.1 | length 121
  Top Layer w20: J8.2@1025,1300 R7.1@1146,1300
NetJ8_7: J8.7 R8.2 | length 106.8
  Top Layer w15: R8.2@818.22,1000 J8.7@925,1000
NetJ9_17: J9.17 R10.2 | length 124.4
  Top Layer w15: R10.2@2500.56,500 J9.17@2625,500
NetnFAULT_2: nFAULT.2 R14.2 | length 116.1
  Top Layer w20: nFAULT.2@1541,160.34 1594.46,106.88 R14.2@1635,106.88
NetNT1_1: NT1.1 R45.2 | length 86.1
  Top Layer w20: R45.2@3226,1808.51 NT1.1@3226,1894.64
NetNT2_1: NT2.1 R54.2 | length 90.8
  Top Layer w20: NT2.1@2432.31,2060.39 R54.2@2523.09,2060.39
NetNT3_1: NT3.1 R53.2 | length 114.8
  Top Layer w20: NT3.1@1312.75,1975.64 1332.75,1975.64 1358.62,2001.51 1358.62,2050.16 R53.2@1365.37,2056.91
NetPVDD_2: PVDD.2 R16.2 | length 92
  Top Layer w15: PVDD.2@1133.2,160.34 R16.2@1225.23,160.34
NetR1_2: R1.2 U1.31 | length 330.8
  Top Layer w10: U1.31@1833.32,1526.84 1920.55,1526.84 1952.12,1495.27 2019.88,1495.27 2048.12,1523.51 2048.12,1529.15 2076.37,1557.39 R1.2@2122,1557.39
NetR19_1: R19.1 R57.2 U2.3 | length 117.2
  Top Layer w20: U2.3@297,917.72 298.81,915.91 298.81,859.75 R19.1@301.56,857 301.56,856.02 323.69,833.88 323.69,819.75 R57.2@329.44,814
NetR23_2: R23.2 U2.4 | length 53.9
  Top Layer w20: U2.4@347,917.72 347,865.16 347.16,865 R23.2@348.31,865
nFAULT: J8.19 R4.2 R14.1 U1.22 | length 2062.5
  Top Layer w8: J8.19@925,400 925,310 v1(939,296) ; R14.1@1635,162 v1(1635,236) 1635,619 v1(1668,652) ; v1(1666,1054.57) 1680,1068.57 1680,1161.07 1707.65,1188.72 1709.61,1188.72 1721.36,1200.47 1721.36,1201.91 1734.9,1215.45 U1.22@1734.9,1349.68
  Power Layer w8: v1(939,296) 999,236 v1(1635,236) ; v1(1666,1054.57) 1666,665 1668,663 v1(1668,652)
nSCS: J9.4 U1.20 | length 1446.6
  Top Layer w8: v1(1612.73,1094.44) 1614.51,1094.44 1647.03,1126.96 1647.03,1197.55 1688,1238.52 1688,1306.02 1693.62,1311.64 1693.62,1317.49 1693.62,1347.77 U1.20@1695.53,1349.68
  Bottom Layer w8: v1(1612.73,1094.44) 1614.51,1094.44 1672.07,1152 2636.94,1152 2682.49,1197.55 2722.55,1197.55 J9.4@2725,1200
nSLEEP: J8.17 U1.21 | length 1390.7
  Top Layer w8: J8.17@925,500 971,546 v1(1088,546) ; v1(1712.18,1266.75) 1715.21,1269.78 U1.21@1715.21,1349.68
  GND Layer w8: v1(1088,546) 1106.61,546 1305.61,745 1359.42,745 1480.19,865.77 v1(1480.19,1068)
  Power Layer w8: v1(1480.19,1068) 1480.19,1210.12 1536.82,1266.75 v1(1712.18,1266.75)
PVDD: J1.3 J6.1 PVDD.1 PVDD_EXT.1 R18.2 R65.2 | length 7709.7
  Top Layer w10: R65.2@1266.49,814.16 1306.81,814.16 1313.82,807.15 v1(1316.53,807.15)
  Top Layer w20: v1(1038,94) 1054.34,77.66 PVDD.1@1133.2,77.66
  Top Layer w30: R18.2@233.44,3506 233.44,3505.02 232.69,3504.27 221.39,3504.27 69.98,3352.85 69.98,3076.4 266.08,2880.3 266.08,2411.03 v1(384,2293.11) 398.42,2278.69 PVDD_EXT.1@483.08,2278.69
  GND Layer w10: J6.1@347.59,600 590.59,843 906.64,843 907.03,843.39 942.97,843.39 943.36,843 1006.64,843 1007.03,843.39 1042.97,843.39 1043.36,843 1280.68,843 v1(1316.53,807.15)
  Power Layer w30: J6.1@347.59,600 347.59,525.41 781,92 1036,92 v1(1038,94)
  Bottom Layer w30: J6.1@347.59,600 347.59,791.5 381.49,825.4 381.49,1865.55 ; v1(384,2293.11) 381.49,2290.6 381.49,1865.55 ; J1.3@2512,1742.58 2512,1815.51 2419.64,1907.87 2353.38,1907.87 2299.64,1854.13 1657.53,1854.13 1615.78,1895.87 1291.31,1895.87 1260.99,1865.55 381.49,1865.55
PVDD_BUCK: C22.1 C30.1 J1.1 J7.1 L1.2 R21.2 | length 3675
  Top Layer w25: J7.1@157,1961 157,1690.89 210.92,1636.97 L1.2@284,1636.97 286.03,1636.97 307.7,1615.3 L1.2@441.48,1615.3 ; L1.2@441.48,1605.47 446.83,1600.12 446.83,1543.25 513,1477.08 513,1214.43 502.81,1204.23 502.81,1203.25 C22.1@499.56,1200 502.81,1196.75 502.81,1170.19 534.31,1138.69 534.31,1130.25 R21.2@537.56,1127 ; L1.2@442.16,1606.15 C30.1@571,1606.15 571,1656 598,1683 v2(610,1683)
  Power Layer w25: v2(610,1683) 897,1683 898,1682 1228,1682 1229,1681 v2(1230,1681)
  Bottom Layer w25: v2(1230,1681) 1230,1388.46 1292.71,1325.75 2328.75,1325.75 2402.16,1399.16 2402.16,1432.74 J1.1@2512,1542.58
SCLK: J8.13 U1.19 | length 1519.5
  Top Layer w8: v1(1613.89,1124.76) 1616.19,1127.06 1616.19,1136.92 1631.16,1151.89 1631.16,1204.13 1672.13,1245.09 1672.13,1312.59 1673.94,1314.4 1673.94,1347.77 U1.19@1675.84,1349.68
  Power Layer w8: v1(841.39,1087.84) 841.39,783.61 J8.13@925,700
  Bottom Layer w8: v1(841.39,1087.84) 839.09,1085.54 839.09,1068.52 861.78,1045.83 1163.5,1045.83 1253.68,1136 1599.4,1136 1610.64,1124.76 v1(1613.89,1124.76)
SDI: J9.12 U1.18 | length 1556.4
  Top Layer w10: v1(1587.69,1113.7) 1589.6,1115.62 1589.6,1134.19 1614.28,1158.88 1614.28,1211.11 1655.25,1252.08 1655.25,1319.58 1655.25,1348.77 U1.18@1656.16,1349.68
  Bottom Layer w10: v1(1587.69,1113.7) 1587.69,1087.14 1728.69,946.13 1876,946.13 1937.33,884.8 1937.33,869 1962.95,843.39 2681.61,843.39 J9.12@2725,800
SDO: J9.14 U1.17 | length 1657.7
  Top Layer w10: v1(1555.76,1114.13) 1557.68,1116.04 1557.68,1127.55 1596.41,1166.28 1596.41,1185.68 1596.41,1218.52 1635.57,1257.68 1635.57,1319.58 1635.57,1348.77 U1.17@1636.47,1349.68
  Bottom Layer w10: v1(1555.76,1114.13) 1544.95,1103.27 1544.95,1057.25 1707.39,894.81 1836.54,894.81 1987.96,743.39 2625,743.39 cw(c2625,700) 2638.23,741.32 2683.68,741.32 2686.61,738.39 J9.14@2725,700
SEN_GVDD: C54.2 J8.20 R86.1 R91.2 U4.1 | length 431.5
  Top Layer w8: R86.1@1266.49,400 1274.43,392.06 U4.1@1453.17,392.06
  Top Layer w15: J8.20@1025,400 C54.2@1146,400 R91.2@1206.25,400 R86.1@1266.49,400
SEN_PVDD: C53.2 J8.12 R65.1 R66.2 U5.4 | length 546
  Top Layer w8: R65.1@1266.49,759.05 1318.2,759.05 1475.92,916.77 1475.92,927.43 U5.4@1476.81,928.32
  Top Layer w15: J8.12@1025,800 1063,762 1143.81,762 C53.2@1146,759.81 1146.83,758.98 1205.86,758.98 R66.2@1206.47,758.38 ; R66.2@1206.25,758.15 R66.2@1206.47,758.38 ; R65.1@1266.49,759.05 1266.05,758.6 1206.69,758.6 R66.2@1206.47,758.38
